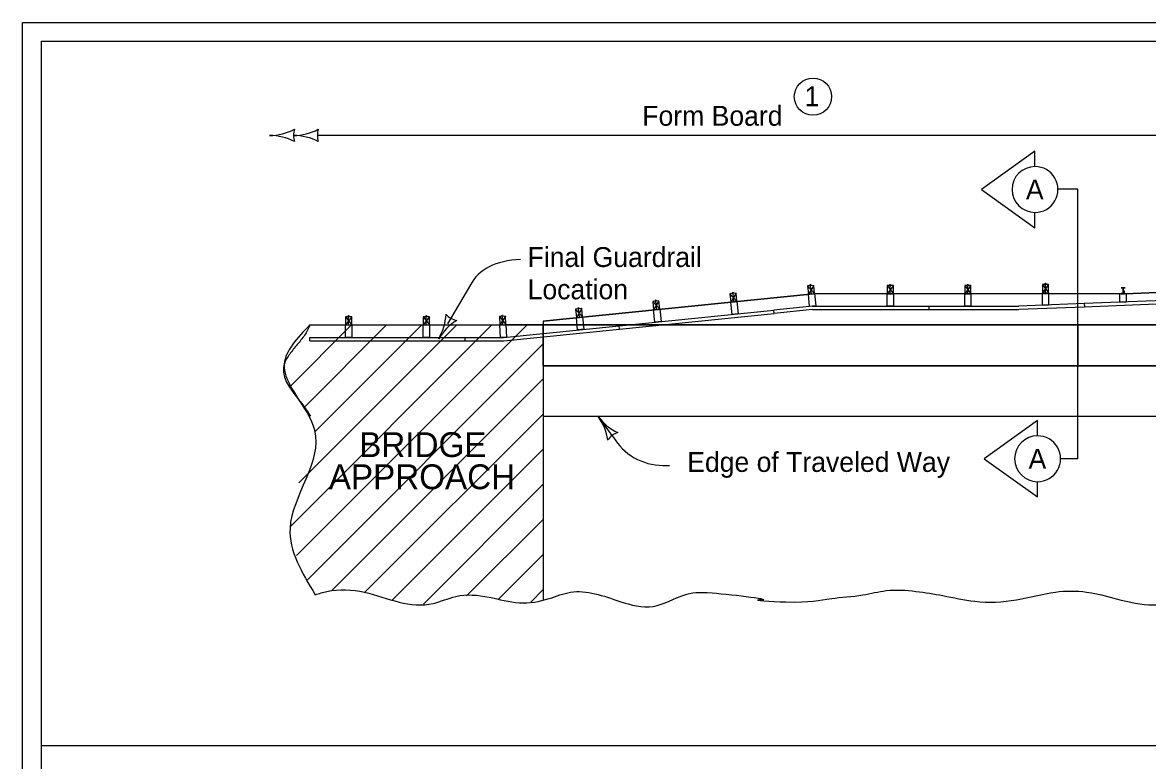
# Model space of a CAD drawing. Extents: x 9538 to 81668, y 7600 to 11751.
# Drawn here: x 20933 to 21839, y 9349 to 9944 of the extents above; entities that cross this region are included whole.
import ezdxf

# ---------------------------------------------------------------- set-up
doc = ezdxf.new("R2010")
doc.units = 0
for name, color, linetype in [('Default', 7, 'Continuous'), ('DsnShtMinorGrid13', 7, 'Continuous'), ('DsnShtMinorGrid14', 7, 'Continuous'), ('DsnShtMinorGrid16', 7, 'Continuous'), ('dsnStdCells', 7, 'Continuous'), ('dsnStdDimension', 7, 'Continuous'), ('dsnStdNameDate', 7, 'Continuous'), ('dsnStdNote', 7, 'Continuous'), ('dsnStdPattern', 7, 'Continuous'), ('dsnStdShading', 7, 'Continuous'), ('dsnStdTable', 7, 'Continuous')]:
    doc.layers.add(name, color=color, linetype=linetype)

msp = doc.modelspace()

# ---------------------------------------------------------------- linework, layer by layer
at = {"layer": 'Default'}
msp.add_lwpolyline([(20932.54, 9944.02), (24067.55, 9944.02), (24067.55, 7924.02), (20932.54, 7924.02)], close=True, dxfattribs=at)
at = {"layer": 'DsnShtMinorGrid13'}
msp.add_circle((21569.21, 9884.28), 15, dxfattribs=at)
at = {"layer": 'DsnShtMinorGrid14'}
for p, q in [((21569.83, 9732.2), (21565.52, 9725.07)), ((21567.25, 9732.92), (21567.24, 9732.99)), ((21631.5, 9733), (21631.5, 9733.07)), ((21694, 9733), (21694, 9733.07)), ((21754, 9732.89), (21759, 9726.23)), ((21759, 9732.89), (21754, 9726.23)), ((21756.5, 9733.86), (21756.5, 9733.93)), ((21756.5, 9726.23), (21756.5, 9732.89)), ((21502.39, 9725.42), (21508.03, 9719.29)), ((21507.37, 9725.92), (21503.06, 9718.79)), ((21504.78, 9726.64), (21504.77, 9726.71)), ((21505.55, 9719.04), (21504.88, 9725.67)), ((21564.86, 9731.7), (21570.49, 9725.56)), ((21565.52, 9725.07), (21570.5, 9725.56)), ((21568.01, 9725.32), (21565.52, 9725.07)), ((21568.01, 9725.32), (21565.52, 9725.07)), ((21566.51, 9715.11), (21565.52, 9725.07)), ((21568.01, 9725.32), (21567.34, 9731.95)), ((21570.5, 9725.56), (21571.49, 9715.61)), ((21629, 9732.03), (21634, 9725.37)), ((21634, 9732.03), (21629, 9725.37)), ((21629, 9725.37), (21634.01, 9725.37)), ((21629, 9715.36), (21629, 9725.37)), ((21631.5, 9725.37), (21631.5, 9732.03)), ((21634.01, 9725.37), (21634.01, 9715.36)), ((21691.5, 9732.03), (21696.5, 9725.37)), ((21696.5, 9732.03), (21691.5, 9725.37)), ((21691.5, 9725.37), (21696.51, 9725.37)), ((21691.5, 9715.36), (21691.5, 9725.37)), ((21694, 9725.37), (21694, 9732.03)), ((21696.51, 9725.37), (21696.51, 9715.36)), ((21754, 9726.23), (21759.01, 9726.23)), ((21754, 9716.22), (21754, 9726.23)), ((21759.01, 9726.23), (21759.01, 9716.22)), ((21380.42, 9714.18), (21380.41, 9714.25)), ((21440.2, 9719.17), (21445.85, 9713.04)), ((21445.18, 9719.67), (21440.87, 9712.54)), ((21442.59, 9720.39), (21442.59, 9720.46)), ((21443.36, 9712.79), (21442.69, 9719.42)), ((21503.06, 9718.79), (21508.04, 9719.29)), ((21504.06, 9708.83), (21503.06, 9718.79)), ((21508.04, 9719.29), (21509.04, 9709.33)), ((21569, 9715.36), (21537.64, 9712.2)), ((21571.49, 9715.61), (21566.51, 9715.11)), ((21569, 9715.36), (21662.75, 9715.36)), ((21634.01, 9715.36), (21629, 9715.36)), ((21662.75, 9712.64), (21662.75, 9715.36)), ((21662.75, 9715.36), (21734.99, 9715.36)), ((21662.75, 9712.65), (21662.75, 9715.36)), ((21696.51, 9715.36), (21691.5, 9715.36)), ((21759.01, 9716.22), (21754, 9716.22)), ((21192.76, 9706.96), (21197.76, 9700.29)), ((21197.76, 9706.96), (21192.76, 9700.29)), ((21195.26, 9707.93), (21195.26, 9708)), ((21195.26, 9700.29), (21195.26, 9706.96)), ((21255.26, 9706.96), (21260.26, 9700.29)), ((21260.26, 9706.96), (21255.26, 9700.29)), ((21257.76, 9707.93), (21257.76, 9708)), ((21257.76, 9700.29), (21257.76, 9706.96)), ((21316.65, 9707.02), (21321.97, 9700.58)), ((21321.64, 9707.27), (21316.98, 9700.33)), ((21319.1, 9708.12), (21319.09, 9708.19)), ((21319.48, 9700.45), (21319.15, 9707.15)), ((21378.03, 9712.96), (21383.67, 9706.79)), ((21383, 9713.46), (21378.69, 9706.29)), ((21378.69, 9706.29), (21383.67, 9706.79)), ((21379.69, 9696.28), (21378.69, 9706.29)), ((21381.18, 9706.54), (21380.51, 9713.21)), ((21383.67, 9706.79), (21384.67, 9696.78)), ((21413.27, 9699.7), (21537.64, 9712.2)), ((21413.54, 9697.01), (21537.91, 9709.51)), ((21440.87, 9712.54), (21445.85, 9713.04)), ((21441.87, 9702.58), (21440.87, 9712.54)), ((21445.85, 9713.04), (21446.85, 9703.08)), ((21509.04, 9709.33), (21504.06, 9708.83)), ((21537.91, 9709.51), (21537.64, 9712.2)), ((21537.91, 9709.52), (21537.64, 9712.2)), ((21569, 9712.65), (21537.91, 9709.52)), ((21569, 9712.65), (21662.75, 9712.65)), ((21662.75, 9712.65), (21735.01, 9712.65)), ((21192.76, 9700.29), (21197.76, 9700.29)), ((21192.76, 9690.28), (21192.76, 9700.29)), ((21197.76, 9700.29), (21197.76, 9690.28)), ((21255.26, 9700.29), (21260.26, 9700.29)), ((21255.26, 9690.28), (21255.26, 9700.29)), ((21260.26, 9700.29), (21260.26, 9690.28)), ((21316.98, 9700.33), (21321.98, 9700.58)), ((21317.48, 9690.28), (21316.98, 9700.33)), ((21319.99, 9690.28), (21413.27, 9699.7)), ((21320.26, 9687.57), (21413.54, 9697)), ((21321.98, 9700.58), (21322.48, 9690.53)), ((21384.67, 9696.78), (21379.69, 9696.28)), ((21413.54, 9697), (21413.27, 9699.7)), ((21413.54, 9697.01), (21413.27, 9699.7)), ((21446.85, 9703.08), (21441.87, 9702.58)), ((21164.01, 9690.28), (21289.01, 9690.28)), ((21164.01, 9687.57), (21164.01, 9690.28)), ((21164.01, 9687.57), (21289.01, 9687.57)), ((21197.76, 9690.28), (21192.76, 9690.28)), ((21260.26, 9690.28), (21255.26, 9690.28)), ((21289.01, 9690.28), (21319.99, 9690.28)), ((21289.01, 9687.57), (21289.01, 9690.28)), ((21289.01, 9687.57), (21320.26, 9687.57)), ((21322.48, 9690.53), (21317.48, 9690.28))]:
    msp.add_line(p, q, dxfattribs=at)
for points in [[(21565.52, 9725.07), (21570.49, 9725.56), (21569.83, 9732.2), (21564.86, 9731.7)], [(21754, 9726.23), (21759, 9726.23), (21759, 9732.89), (21754, 9732.89)], [(21503.06, 9718.79), (21508.03, 9719.29), (21507.37, 9725.92), (21502.39, 9725.42)], [(21629, 9725.37), (21634, 9725.37), (21634, 9732.03), (21629, 9732.03)], [(21691.5, 9725.37), (21696.5, 9725.37), (21696.5, 9732.03), (21691.5, 9732.03)], [(21440.87, 9712.54), (21445.85, 9713.04), (21445.18, 9719.67), (21440.2, 9719.17)], [(21192.76, 9700.29), (21197.76, 9700.29), (21197.76, 9706.96), (21192.76, 9706.96)], [(21255.26, 9700.29), (21260.26, 9700.29), (21260.26, 9706.96), (21255.26, 9706.96)], [(21316.98, 9700.33), (21321.97, 9700.58), (21321.64, 9707.27), (21316.65, 9707.02)], [(21378.69, 9706.29), (21383.67, 9706.79), (21383, 9713.46), (21378.03, 9712.96)]]:
    msp.add_lwpolyline(points, close=True, dxfattribs=at)
for points in [[(21567.01, 9731.92), (21566.97, 9732.34), (21567.63, 9732.41), (21567.67, 9731.98)], [(21567.11, 9732.36), (21567.05, 9732.9), (21567.44, 9732.94), (21567.49, 9732.4)], [(21631.17, 9732.03), (21631.17, 9732.46), (21631.84, 9732.46), (21631.84, 9732.03)], [(21631.31, 9732.46), (21631.31, 9733), (21631.7, 9733), (21631.7, 9732.46)], [(21693.67, 9732.03), (21693.67, 9732.46), (21694.34, 9732.46), (21694.34, 9732.03)], [(21693.81, 9732.46), (21693.81, 9733), (21694.2, 9733), (21694.2, 9732.46)], [(21756.17, 9732.89), (21756.17, 9733.32), (21756.84, 9733.32), (21756.84, 9732.89)], [(21756.31, 9733.32), (21756.31, 9733.86), (21756.7, 9733.86), (21756.7, 9733.32)], [(21504.55, 9725.64), (21504.5, 9726.07), (21505.17, 9726.13), (21505.21, 9725.7)], [(21504.64, 9726.08), (21504.59, 9726.62), (21504.97, 9726.66), (21505.03, 9726.12)], [(21380.28, 9713.62), (21380.22, 9714.16), (21380.61, 9714.2), (21380.66, 9713.66)], [(21442.36, 9719.39), (21442.32, 9719.82), (21442.98, 9719.88), (21443.02, 9719.45)], [(21442.46, 9719.83), (21442.4, 9720.37), (21442.79, 9720.41), (21442.84, 9719.87)], [(21194.93, 9706.96), (21194.93, 9707.39), (21195.59, 9707.39), (21195.59, 9706.96)], [(21195.06, 9707.39), (21195.06, 9707.93), (21195.45, 9707.93), (21195.45, 9707.39)], [(21257.43, 9706.96), (21257.43, 9707.39), (21258.09, 9707.39), (21258.09, 9706.96)], [(21257.56, 9707.39), (21257.56, 9707.93), (21257.95, 9707.93), (21257.95, 9707.39)], [(21318.81, 9707.13), (21318.79, 9707.56), (21319.46, 9707.59), (21319.48, 9707.16)], [(21318.93, 9707.57), (21318.9, 9708.11), (21319.29, 9708.13), (21319.32, 9707.59)], [(21380.18, 9713.17), (21380.14, 9713.61), (21380.8, 9713.67), (21380.85, 9713.24)], [(21319.48, 9700.45), (21316.98, 9700.33), (21316.98, 9700.33)]]:
    msp.add_lwpolyline(points, dxfattribs=at)
at = {"layer": 'DsnShtMinorGrid16'}
for p, q in [((22249.57, 9742.98), (21820.72, 9725.37)), ((21820.72, 9725.37), (21569.54, 9725.37)), ((21352.01, 9700.29), (22296.11, 9700.29))]:
    msp.add_line(p, q, dxfattribs=at)
msp.add_lwpolyline([(21569.54, 9725.37), (21352.01, 9703.35), (21352.01, 9700.29)], dxfattribs=at)
for points in [[(21352.01, 9667.31), (21352.01, 9700.29), (21782.63, 9700.29), (21782.63, 9667.31)], [(22296.11, 9700.29), (22296.11, 9667.31), (21782.63, 9667.31), (21782.63, 9700.29)]]:
    msp.add_lwpolyline(points, close=True, dxfattribs=at)
at = {"layer": 'dsnStdCells'}
for p, q in [((21816.45, 9718.72), (21816.45, 9725.68)), ((21816.45, 9725.68), (21817.07, 9725.68)), ((21817.07, 9725.37), (21817.07, 9725.68)), ((21820.82, 9725.37), (21817.07, 9725.37)), ((21820.72, 9730.26), (21817.39, 9730.26)), ((21817.39, 9730.26), (21817.39, 9730.1)), ((21817.39, 9730.26), (21817.39, 9730.1)), ((21820.72, 9730.26), (21817.39, 9730.26)), ((21817.39, 9730.1), (21818.56, 9730.1)), ((21817.39, 9730.1), (21818.56, 9730.1)), ((21818.56, 9725.52), (21817.39, 9725.52)), ((21817.39, 9725.52), (21817.39, 9725.37)), ((21817.39, 9725.52), (21817.39, 9725.37)), ((21818.56, 9725.52), (21817.39, 9725.52)), ((21817.39, 9725.37), (21820.72, 9725.37)), ((21817.39, 9725.37), (21820.72, 9725.37)), ((21818.97, 9729.69), (21818.97, 9725.94)), ((21818.97, 9729.69), (21818.97, 9725.94)), ((21819.13, 9725.94), (21819.13, 9729.69)), ((21819.13, 9725.94), (21819.13, 9729.69)), ((21819.37, 9726.04), (21819.28, 9725.99)), ((21819.37, 9726.04), (21819.28, 9725.99)), ((21819.28, 9725.99), (21819.28, 9725.61)), ((21819.28, 9725.61), (21819.28, 9725.99)), ((21819.37, 9726.04), (21820.33, 9726.04)), ((21820.33, 9726.04), (21819.37, 9726.04)), ((21819.55, 9730.1), (21820.72, 9730.1)), ((21819.55, 9730.1), (21820.72, 9730.1)), ((21820.72, 9725.52), (21819.55, 9725.52)), ((21820.72, 9725.52), (21819.55, 9725.52)), ((21819.59, 9725.99), (21819.59, 9725.57)), ((21819.59, 9725.57), (21819.59, 9725.99)), ((21819.59, 9725.57), (21819.59, 9725.99)), ((21820.15, 9727.55), (21819.63, 9727.55)), ((21819.63, 9727.55), (21819.63, 9726.04)), ((21820.15, 9727.55), (21819.63, 9727.55)), ((21819.63, 9727.55), (21819.63, 9726.04)), ((21819.63, 9726.04), (21820.15, 9726.04)), ((21820.15, 9726.04), (21820.15, 9727.55)), ((21820.15, 9726.04), (21820.15, 9727.55)), ((21820.19, 9725.57), (21820.19, 9725.99)), ((21820.19, 9725.99), (21820.19, 9725.57)), ((21820.19, 9725.57), (21820.19, 9725.99)), ((21820.33, 9726.04), (21820.4, 9726.04)), ((21820.4, 9726.04), (21820.33, 9726.04)), ((21820.49, 9725.99), (21820.4, 9726.04)), ((21820.49, 9725.99), (21820.4, 9726.04)), ((21820.4, 9725.52), (21820.49, 9725.57)), ((21820.4, 9725.52), (21820.49, 9725.57)), ((21820.49, 9725.57), (21820.49, 9725.99)), ((21820.49, 9725.57), (21820.49, 9725.99)), ((21820.72, 9730.1), (21820.72, 9730.26)), ((21820.72, 9730.1), (21820.72, 9730.26)), ((21820.72, 9725.37), (21820.72, 9725.52)), ((21820.72, 9725.37), (21820.72, 9725.52)), ((21820.82, 9725.68), (21821.45, 9725.68)), ((21820.82, 9725.68), (21820.82, 9725.37)), ((21821.45, 9725.68), (21821.45, 9718.72)), ((21821.45, 9718.72), (21816.45, 9718.72))]:
    msp.add_line(p, q, dxfattribs=at)
for points in [[(21819.28, 9725.61), (21819.28, 9725.61)], [(21819.55, 9725.52), (21820.4, 9725.52), (21820.4, 9725.52)]]:
    msp.add_lwpolyline(points, dxfattribs=at)
for centre, start, end in [((21818.56, 9729.69), 359.99336, 90.00253), ((21818.56, 9729.69), 359.99336, 90.00253), ((21818.56, 9725.94), 270.00734, 359.99635), ((21818.56, 9725.94), 270.00734, 359.99635), ((21819.55, 9729.69), 90.00734, 179.99635), ((21819.55, 9729.69), 90.00734, 179.99635), ((21819.55, 9725.94), 179.99336, 270.00253), ((21819.55, 9725.94), 179.99336, 270.00253), ((21819.55, 9725.94), 230.88662, 270.00253)]:
    msp.add_arc(centre, 0.417, start, end, dxfattribs=at)
for points in [[(21819.59, 9725.99), (21819.56, 9726), (21819.51, 9726.03), (21819.43, 9726.05), (21819.35, 9726.03), (21819.31, 9726), (21819.28, 9725.99)], [(21819.59, 9725.99), (21819.56, 9726), (21819.51, 9726.03), (21819.43, 9726.05), (21819.35, 9726.03), (21819.31, 9726), (21819.28, 9725.99)], [(21819.28, 9725.99), (21819.31, 9726), (21819.35, 9726.03), (21819.43, 9726.05), (21819.51, 9726.03), (21819.56, 9726), (21819.59, 9725.99)], [(21819.49, 9725.53), (21819.5, 9725.53), (21819.53, 9725.54), (21819.56, 9725.56), (21819.59, 9725.57)], [(21820.19, 9725.99), (21820.13, 9726), (21820.03, 9726.03), (21819.87, 9726.04), (21819.72, 9726.03), (21819.63, 9726), (21819.59, 9725.99)], [(21820.19, 9725.99), (21820.13, 9726), (21820.03, 9726.03), (21819.87, 9726.04), (21819.72, 9726.03), (21819.63, 9726), (21819.59, 9725.99)], [(21819.59, 9725.99), (21819.63, 9726), (21819.72, 9726.03), (21819.87, 9726.04), (21820.03, 9726.03), (21820.13, 9726), (21820.19, 9725.99)], [(21819.59, 9725.57), (21819.64, 9725.56), (21819.74, 9725.53), (21819.9, 9725.52), (21820.05, 9725.54), (21820.14, 9725.56), (21820.19, 9725.57)], [(21820.19, 9725.57), (21820.14, 9725.56), (21820.05, 9725.54), (21819.9, 9725.52), (21819.74, 9725.53), (21819.64, 9725.56), (21819.59, 9725.57)], [(21819.59, 9725.57), (21819.64, 9725.56), (21819.74, 9725.53), (21819.9, 9725.52), (21820.05, 9725.54), (21820.14, 9725.56), (21820.19, 9725.57)], [(21820.49, 9725.99), (21820.47, 9726), (21820.44, 9726.02), (21820.37, 9726.04), (21820.3, 9726.04), (21820.24, 9726.02), (21820.2, 9726), (21820.19, 9725.99)], [(21820.49, 9725.99), (21820.47, 9726), (21820.44, 9726.02), (21820.37, 9726.04), (21820.3, 9726.04), (21820.24, 9726.02), (21820.2, 9726), (21820.19, 9725.99)], [(21820.19, 9725.99), (21820.2, 9726), (21820.24, 9726.02), (21820.3, 9726.04), (21820.37, 9726.04), (21820.44, 9726.02), (21820.47, 9726), (21820.49, 9725.99)], [(21820.19, 9725.57), (21820.2, 9725.57), (21820.23, 9725.55), (21820.3, 9725.52), (21820.37, 9725.52), (21820.44, 9725.54), (21820.47, 9725.56), (21820.49, 9725.57)], [(21820.49, 9725.57), (21820.47, 9725.56), (21820.44, 9725.54), (21820.37, 9725.52), (21820.3, 9725.52), (21820.23, 9725.55), (21820.2, 9725.57), (21820.19, 9725.57)], [(21820.19, 9725.57), (21820.2, 9725.57), (21820.23, 9725.55), (21820.3, 9725.52), (21820.37, 9725.52), (21820.44, 9725.54), (21820.47, 9725.56), (21820.49, 9725.57)]]:
    msp.add_open_spline(points, degree=3, dxfattribs=at)
at = {"layer": 'dsnStdDimension'}
msp.add_line((21170.82, 9853.15), (22193.23, 9853.15), dxfattribs=at)
for centre, radius, start, end in [((21131.6, 9895.5), 42.5, 270, 298.07249), ((21131.6, 9810.5), 42.5, 61.92751, 90), ((21150.82, 9895.5), 42.5, 270, 298.07249), ((21167.23, 9853), 16.42, 162.26665, 197.73335), ((21150.82, 9810.5), 42.5, 61.92751, 90), ((21186.45, 9853), 16.42, 162.26665, 197.73335)]:
    msp.add_arc(centre, radius, start, end, dxfattribs=at)
at = {"layer": 'dsnStdNameDate'}
for p, q in [((21197.55, 9700.29), (21147.49, 9650.22)), ((21310.69, 9700.29), (21147.88, 9537.48)), ((21338.97, 9700.29), (21153.18, 9514.49)), ((21282.41, 9700.29), (21155.11, 9573)), ((21225.84, 9700.29), (21159.59, 9634.05)), ((21254.12, 9700.29), (21167.68, 9613.85)), ((22353.67, 9700.29), (21321.75, 9700.29)), ((21352.01, 9685.04), (21161.44, 9494.47)), ((21352.01, 9656.76), (21181.35, 9486.1)), ((21352.01, 9628.48), (21208.41, 9484.87)), ((21352.01, 9600.19), (21230.15, 9478.33)), ((21352.01, 9571.91), (21255.47, 9475.36)), ((21352.01, 9543.62), (21290.29, 9481.9)), ((21352.01, 9515.34), (21316.17, 9479.5)), ((21352.01, 9487.05), (21341.99, 9477.03)), ((23103.12, 9361.02), (20947.54, 9361.02))]:
    msp.add_line(p, q, dxfattribs=at)
at = {"layer": 'dsnStdNote'}
for p, q in [((21293.52, 9732.66), (21274.97, 9701.32)), ((21408.24, 9610.21), (21396.12, 9626.66)), ((21448.32, 9587.14), (21453.77, 9587.14))]:
    msp.add_line(p, q, dxfattribs=at)
for centre, radius, start, end in [((21231.21, 9710.82), 42.5, 329.37973, 357.45222), ((21285.93, 9719.84), 16.42, 221.64638, 257.11308), ((21304.36, 9667.53), 42.5, 121.30724, 149.37973), ((21430.34, 9651.86), 42.5, 216.37256, 244.44505), ((21361.9, 9601.45), 42.5, 8.30007, 36.37256), ((21417.26, 9597.97), 16.42, 108.63921, 144.10591), ((21448.38, 9633.6), 46.46, 210.22743, 270)]:
    msp.add_arc(centre, radius, start, end, dxfattribs=at)
msp.add_ellipse((21374.61, 9693.62), major_axis=(-81.09, 39.04), ratio=0.555556, start_param=5.482641, end_param=6.283185, dxfattribs=at)
at = {"layer": 'dsnStdPattern'}
for p, q in [((21782.63, 9809.76), (21766.85, 9809.76)), ((21782.63, 9592.47), (21782.63, 9809.76)), ((21782.63, 9592.47), (21768.67, 9592.47))]:
    msp.add_line(p, q, dxfattribs=at)
for points in [[(21748.06, 9827.94), (21748.06, 9840.26), (21704.93, 9809.45), (21748.06, 9778.64), (21748.06, 9790.97)], [(21750.19, 9610.96), (21750.19, 9623.28), (21707.05, 9592.47), (21750.19, 9561.66), (21750.19, 9573.99)]]:
    msp.add_lwpolyline(points, dxfattribs=at)
for centre, start, end in [((21748.06, 9809.45), 90.00083, 269.99917), ((21748.06, 9809.45), 269.99917, 90.00083), ((21750.19, 9592.47), 90.00083, 269.99917), ((21750.19, 9592.47), 269.99917, 90.00083)]:
    msp.add_arc(centre, 18.49, start, end, dxfattribs=at)
at = {"layer": 'dsnStdShading'}
for q in [(20947.54, 8319.02), (24043.23, 9929.02)]:
    msp.add_line((20947.54, 9929.02), q, dxfattribs=at)
at = {"layer": 'dsnStdTable'}
for p, q in [((21820.72, 9725.37), (22296.11, 9744.89)), ((22199.32, 9733.93), (21787.75, 9717.47)), ((21352.01, 9703.35), (21569.54, 9725.37)), ((21817.39, 9725.37), (21569.54, 9725.37)), ((22199.43, 9731.22), (21787.75, 9714.76)), ((21816.45, 9718.72), (21816.45, 9725.68)), ((21816.45, 9725.68), (21817.07, 9725.68)), ((21817.07, 9725.37), (21817.07, 9725.68)), ((21820.82, 9725.37), (21817.07, 9725.37)), ((21817.39, 9730.26), (21817.39, 9730.1)), ((21820.72, 9730.26), (21817.39, 9730.26)), ((21817.39, 9730.1), (21818.56, 9730.1)), ((21817.39, 9725.52), (21817.39, 9725.37)), ((21818.56, 9725.52), (21817.39, 9725.52)), ((21817.39, 9725.37), (21820.72, 9725.37)), ((21818.97, 9729.69), (21818.97, 9725.94)), ((21819.13, 9725.94), (21819.13, 9729.69)), ((21819.37, 9726.04), (21819.28, 9725.99)), ((21819.28, 9725.61), (21819.28, 9725.99)), ((21819.37, 9726.04), (21820.33, 9726.04)), ((21819.55, 9730.1), (21820.72, 9730.1)), ((21820.72, 9725.52), (21819.55, 9725.52)), ((21819.59, 9725.57), (21819.59, 9725.99)), ((21820.15, 9727.55), (21819.63, 9727.55)), ((21819.63, 9727.55), (21819.63, 9726.04)), ((21820.15, 9726.04), (21820.15, 9727.55)), ((21820.19, 9725.57), (21820.19, 9725.99)), ((21820.33, 9726.04), (21820.4, 9726.04)), ((21820.49, 9725.99), (21820.4, 9726.04)), ((21820.4, 9725.52), (21820.49, 9725.57)), ((21820.49, 9725.57), (21820.49, 9725.99)), ((21820.72, 9730.1), (21820.72, 9730.26)), ((21820.72, 9725.37), (21820.72, 9725.52)), ((21820.82, 9725.68), (21821.45, 9725.68)), ((21820.82, 9725.68), (21820.82, 9725.37)), ((21821.45, 9725.68), (21821.45, 9718.72)), ((21787.75, 9717.47), (21734.99, 9715.36)), ((21787.86, 9714.76), (21735.01, 9712.65)), ((21787.75, 9717.47), (21787.86, 9714.76)), ((21787.75, 9717.47), (21787.86, 9714.76)), ((21821.45, 9718.72), (21816.45, 9718.72)), ((21164.01, 9700.29), (21321.75, 9700.29)), ((21164.01, 9700.29), (21352.01, 9700.29)), ((21352.01, 9703.35), (21352.01, 9478.83)), ((21352.01, 9667.31), (22790.48, 9667.31)), ((21352.01, 9626.66), (22778.02, 9626.66))]:
    msp.add_line(p, q, dxfattribs=at)
for centre, start, end in [((21818.56, 9729.69), 359.99336, 90.00253), ((21818.56, 9725.94), 270.00734, 359.99635), ((21819.55, 9729.69), 90.00734, 179.99635), ((21819.55, 9725.94), 264.71743, 270.00253)]:
    msp.add_arc(centre, 0.417, start, end, dxfattribs=at)
for points in [[(21819.59, 9725.99), (21819.56, 9726), (21819.51, 9726.03), (21819.43, 9726.05), (21819.35, 9726.03), (21819.31, 9726), (21819.28, 9725.99)], [(21819.49, 9725.53), (21819.5, 9725.53), (21819.53, 9725.54), (21819.56, 9725.56), (21819.59, 9725.57)], [(21820.19, 9725.99), (21820.13, 9726), (21820.03, 9726.03), (21819.87, 9726.04), (21819.72, 9726.03), (21819.63, 9726), (21819.59, 9725.99)], [(21819.59, 9725.57), (21819.64, 9725.56), (21819.74, 9725.53), (21819.9, 9725.52), (21820.05, 9725.54), (21820.14, 9725.56), (21820.19, 9725.57)], [(21820.49, 9725.99), (21820.47, 9726), (21820.44, 9726.02), (21820.37, 9726.04), (21820.3, 9726.04), (21820.24, 9726.02), (21820.2, 9726), (21820.19, 9725.99)], [(21820.19, 9725.57), (21820.2, 9725.57), (21820.23, 9725.55), (21820.3, 9725.52), (21820.37, 9725.52), (21820.44, 9725.54), (21820.47, 9725.56), (21820.49, 9725.57)]]:
    msp.add_open_spline(points, degree=3, dxfattribs=at)
for points in [[(21164.01, 9700.29), (21143.36, 9668.74), (21167.72, 9615.65), (21148.02, 9536.55), (21168.3, 9482.94)], [(21164.01, 9700.29), (21162.21, 9696.07), (21159.76, 9692.06), (21153.77, 9684.41), (21147.74, 9676.81), (21145.23, 9672.86), (21144.21, 9670.83), (21143.76, 9669.79), (21143.55, 9669.26), (21143.45, 9669), (21143.36, 9668.74), (21143.52, 9658.28), (21149.21, 9647.75), (21157.25, 9637.18), (21161.16, 9631.91), (21164.47, 9626.66)], [(21168.3, 9482.94), (21177.72, 9485.52), (21207.94, 9484.95), (21235.89, 9476.96), (21263.26, 9475.82), (21281.5, 9481.53), (21308.3, 9480.96), (21332.83, 9476.39), (21356.77, 9479.81), (21373.88, 9484.95), (21413.8, 9477.53), (21440.6, 9473.54), (21465.12, 9482.67), (21487.93, 9484.38), (21526.7, 9478.67), (21526.13, 9478.67), (21547.29, 9477.07), (21584.35, 9479.92), (21609.44, 9482.78), (21628.26, 9486.2), (21652.21, 9485.63), (21673.88, 9482.21), (21699.54, 9477.64), (21733.18, 9478.78), (21764.55, 9485.06), (21789.64, 9485.06), (21821.57, 9477.64), (21850.65, 9474.79), (21884.29, 9481.63), (21916.8, 9485.06), (21951.01, 9478.21), (21976.67, 9475.36), (21998.91, 9478.78), (22026.85, 9494.19), (22037.11, 9496.47), (22061.63, 9498.75), (22092.3, 9499.32), (22113.4, 9499.32), (22166.71, 9490.03)]]:
    msp.add_spline(points, degree=3, dxfattribs=at)

# ---------------------------------------------------------------- texts
at = {"layer": 'DsnShtMinorGrid13'}
msp.add_text('1', height=16, dxfattribs=at).set_placement((21562.47, 9876.52))
at = {"layer": 'dsnStdDimension'}
msp.add_text('Form Board', height=16, dxfattribs=at).set_placement((21431.77, 9860.84))
at = {"layer": 'dsnStdNote'}
for s, height, p in [('Final Guardrail ', 16, (21339.42, 9746.99)), ('Location', 16, (21339.42, 9720.99)), ('BRIDGE', 20, (21203.73, 9593.85)), ('Edge of Traveled Way', 16, (21467.96, 9581.87)), ('APPROACH', 20, (21179.26, 9567.96))]:
    msp.add_text(s, height=height, dxfattribs=at).set_placement(p)
at = {"layer": 'dsnStdPattern'}
for p in [(21740.79, 9801.45), (21742.89, 9584.47)]:
    msp.add_text('A', height=16, dxfattribs=at).set_placement(p)

doc.saveas('drawing.dxf')
